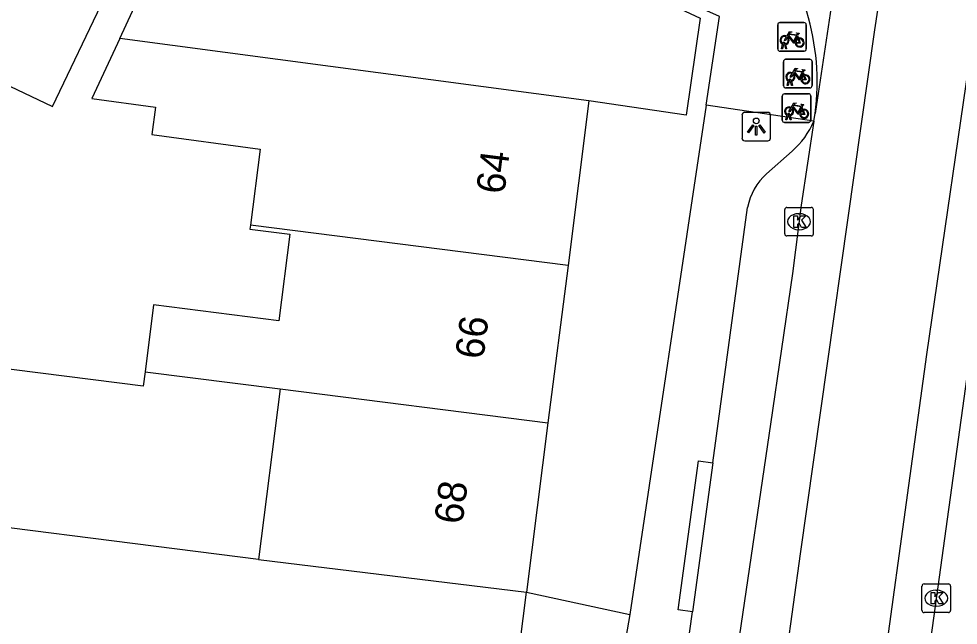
# Model space of a CAD drawing. Extents: x 160356 to 161355, y 381727 to 382845.
# Drawn here: x 160853.83 to 160886.69, y 382411.12 to 382432.34 of the extents above; entities that cross this region are included whole.
import ezdxf

# ---------------------------------------------------------------- set-up
doc = ezdxf.new("R2010")
doc.units = 0
for name, color, linetype in [('IMGEO_Fietsenrek', 7, 'Continuous'), ('IMGEO_Kolk', 7, 'Continuous'), ('IMGEO_Lichtpunt', 7, 'Continuous'), ('IMGEO_Pand', 7, 'Continuous'), ('IMGEO_Pand_nummerreeks', 7, 'Continuous'), ('IMGEO_Rijbaan_lokaal_gesloten', 7, 'Continuous'), ('IMGEO_Rijbaan_lokaal_open', 7, 'Continuous'), ('IMGEO_Voetpad_open', 7, 'Continuous')]:
    doc.layers.add(name, color=color, linetype=linetype)

msp = doc.modelspace()

# ---------------------------------------------------------------- linework, layer by layer
at = {"layer": 'IMGEO_Fietsenrek'}
for p, q in [((160880.382, 382431.286), (160880.382, 382432.127)), ((160880.382, 382432.127), (160880.382, 382431.286)), ((160880.457, 382432.211), (160881.298, 382432.211)), ((160881.298, 382432.211), (160880.457, 382432.211)), ((160881.382, 382432.136), (160881.382, 382431.295)), ((160881.382, 382431.295), (160881.382, 382432.136)), ((160881.069, 382431.76), (160881.105, 382431.665)), ((160880.509, 382431.295), (160880.548, 382431.455)), ((160880.578, 382431.443), (160880.543, 382431.295)), ((160880.62, 382431.467), (160880.619, 382431.471)), ((160880.661, 382431.295), (160880.627, 382431.437)), ((160880.651, 382431.478), (160880.652, 382431.471)), ((160880.659, 382431.441), (160880.694, 382431.295)), ((160881.307, 382431.211), (160880.466, 382431.211)), ((160880.466, 382431.211), (160881.307, 382431.211)), ((160880.543, 382431.295), (160880.509, 382431.295)), ((160880.694, 382431.295), (160880.661, 382431.295)), ((160880.583, 382429.999), (160880.583, 382430.84)), ((160880.583, 382430.84), (160880.583, 382429.999)), ((160880.658, 382430.924), (160881.499, 382430.924)), ((160881.499, 382430.924), (160880.658, 382430.924)), ((160881.583, 382430.849), (160881.583, 382430.008)), ((160881.583, 382430.008), (160881.583, 382430.849)), ((160881.27, 382430.473), (160881.306, 382430.378)), ((160880.71, 382430.008), (160880.749, 382430.168)), ((160880.779, 382430.156), (160880.744, 382430.008)), ((160880.821, 382430.18), (160880.82, 382430.184)), ((160880.862, 382430.008), (160880.828, 382430.15)), ((160880.852, 382430.191), (160880.853, 382430.184)), ((160880.86, 382430.154), (160880.895, 382430.008)), ((160880.614, 382429.717), (160881.455, 382429.717)), ((160881.455, 382429.717), (160880.614, 382429.717)), ((160881.508, 382429.924), (160880.667, 382429.924)), ((160880.667, 382429.924), (160881.508, 382429.924)), ((160880.744, 382430.008), (160880.71, 382430.008)), ((160880.895, 382430.008), (160880.862, 382430.008)), ((160880.539, 382428.792), (160880.539, 382429.633)), ((160880.539, 382429.633), (160880.539, 382428.792)), ((160881.539, 382429.642), (160881.539, 382428.801)), ((160881.539, 382428.801), (160881.539, 382429.642)), ((160881.226, 382429.266), (160881.262, 382429.171)), ((160881.464, 382428.717), (160880.623, 382428.717)), ((160880.623, 382428.717), (160881.464, 382428.717)), ((160880.666, 382428.801), (160880.705, 382428.961)), ((160880.7, 382428.801), (160880.666, 382428.801)), ((160880.735, 382428.949), (160880.7, 382428.801)), ((160880.777, 382428.973), (160880.776, 382428.977)), ((160880.818, 382428.801), (160880.784, 382428.943)), ((160880.808, 382428.984), (160880.809, 382428.977)), ((160880.816, 382428.947), (160880.851, 382428.801)), ((160880.851, 382428.801), (160880.818, 382428.801))]:
    msp.add_line(p, q, dxfattribs=at)
for points in [[(160880.716, 382431.685), (160880.664, 382431.595), (160880.624, 382431.57), (160880.625, 382431.617), (160880.68, 382431.711)], [(160880.695, 382431.737), (160880.79, 382431.901), (160880.876, 382431.887), (160880.878, 382431.878), (160880.822, 382431.867), (160880.795, 382431.822), (160881.051, 382431.781)], [(160880.991, 382431.493), (160880.941, 382431.493), (160880.75, 382431.744), (160880.731, 382431.712)], [(160881.038, 382431.756), (160880.781, 382431.797), (160880.764, 382431.768), (160880.931, 382431.548), (160881.038, 382431.756)], [(160881.086, 382431.658), (160881.056, 382431.735), (160880.947, 382431.517), (160880.99, 382431.517)], [(160881.051, 382431.781), (160881.076, 382431.83), (160881.07, 382431.834), (160881.047, 382431.838), (160881.035, 382431.845), (160881.034, 382431.848), (160881.036, 382431.853), (160881.131, 382431.838), (160881.133, 382431.828), (160881.123, 382431.815), (160881.111, 382431.809), (160881.097, 382431.815), (160881.069, 382431.76)], [(160881.02, 382431.517), (160881.14, 382431.516), (160881.096, 382431.63)], [(160881.116, 382431.637), (160881.171, 382431.492), (160881.021, 382431.492)], [(160880.917, 382430.398), (160880.865, 382430.308), (160880.825, 382430.283), (160880.826, 382430.33), (160880.881, 382430.424)], [(160880.896, 382430.45), (160880.991, 382430.614), (160881.077, 382430.6), (160881.079, 382430.591), (160881.023, 382430.58), (160880.996, 382430.535), (160881.252, 382430.494)], [(160881.192, 382430.206), (160881.142, 382430.206), (160880.951, 382430.457), (160880.932, 382430.425)], [(160881.239, 382430.469), (160880.982, 382430.51), (160880.965, 382430.481), (160881.132, 382430.261), (160881.239, 382430.469)], [(160881.287, 382430.371), (160881.257, 382430.448), (160881.148, 382430.23), (160881.191, 382430.23)], [(160881.221, 382430.23), (160881.341, 382430.229), (160881.297, 382430.343)], [(160881.317, 382430.35), (160881.372, 382430.205), (160881.222, 382430.205)], [(160881.252, 382430.494), (160881.277, 382430.543), (160881.271, 382430.547), (160881.248, 382430.551), (160881.236, 382430.558), (160881.235, 382430.561), (160881.237, 382430.566), (160881.332, 382430.551), (160881.334, 382430.541), (160881.324, 382430.528), (160881.312, 382430.522), (160881.298, 382430.528), (160881.27, 382430.473)], [(160880.852, 382429.243), (160880.947, 382429.407), (160881.033, 382429.393), (160881.035, 382429.384), (160880.979, 382429.373), (160880.952, 382429.328), (160881.208, 382429.287)], [(160881.208, 382429.287), (160881.233, 382429.336), (160881.227, 382429.34), (160881.204, 382429.344), (160881.192, 382429.351), (160881.191, 382429.354), (160881.193, 382429.359), (160881.288, 382429.344), (160881.29, 382429.334), (160881.28, 382429.321), (160881.268, 382429.315), (160881.254, 382429.321), (160881.226, 382429.266)], [(160880.873, 382429.191), (160880.821, 382429.101), (160880.781, 382429.076), (160880.782, 382429.123), (160880.837, 382429.217)], [(160881.148, 382428.999), (160881.098, 382428.999), (160880.907, 382429.25), (160880.888, 382429.218)], [(160881.195, 382429.262), (160880.938, 382429.303), (160880.921, 382429.274), (160881.088, 382429.054), (160881.195, 382429.262)], [(160881.243, 382429.164), (160881.213, 382429.241), (160881.104, 382429.023), (160881.147, 382429.023)], [(160881.177, 382429.023), (160881.297, 382429.022), (160881.253, 382429.136)], [(160881.273, 382429.143), (160881.328, 382428.998), (160881.178, 382428.998)]]:
    msp.add_lwpolyline(points, dxfattribs=at)
for centre, radius, start, end in [((160880.46, 382432.133), 0.0779, 92.4484, 184.2845), ((160880.46, 382432.133), 0.0779, 92.4484, 184.2845), ((160881.304, 382432.133), 0.0779, 2.4484, 94.2845), ((160881.304, 382432.133), 0.0779, 2.4484, 94.2845), ((160880.622, 382431.596), 0.159, 62.6766, 242.1369), ((160880.622, 382431.596), 0.129, 63.3192, 238.903), ((160880.622, 382431.596), 0.129, 283.6043, 43.4302), ((160880.622, 382431.596), 0.159, 283.5766, 46.6042), ((160881.149, 382431.512), 0.159, 113.3408, 178.3217), ((160881.149, 382431.512), 0.159, 187.0065, 105.7708), ((160880.602, 382431.467), 0.0499, 12.8025, 158.6934), ((160880.622, 382431.596), 0.159, 253.9967, 271.7867), ((160880.602, 382431.467), 0.0174, 12.8025, 163.4502), ((160880.622, 382431.596), 0.129, 253.415, 269.0204), ((160881.149, 382431.512), 0.129, 113.923, 177.9556), ((160881.149, 382431.512), 0.129, 188.6715, 104.5883), ((160880.46, 382431.289), 0.0779, 182.4484, 274.2845), ((160880.46, 382431.289), 0.0779, 182.4484, 274.2845), ((160881.304, 382431.289), 0.0779, 272.4484, 4.2845), ((160881.304, 382431.289), 0.0779, 272.4484, 4.2845), ((160880.661, 382430.846), 0.0779, 92.4484, 184.2845), ((160880.661, 382430.846), 0.0779, 92.4484, 184.2845), ((160881.505, 382430.846), 0.0779, 2.4484, 94.2845), ((160881.505, 382430.846), 0.0779, 2.4484, 94.2845), ((160880.823, 382430.309), 0.159, 62.6766, 242.1369), ((160880.823, 382430.309), 0.129, 63.3192, 238.903), ((160880.823, 382430.309), 0.129, 283.6043, 43.4302), ((160880.823, 382430.309), 0.159, 283.5766, 46.6042), ((160881.35, 382430.225), 0.159, 113.3408, 178.3217), ((160881.35, 382430.225), 0.159, 187.0065, 105.7708), ((160881.35, 382430.225), 0.129, 113.923, 177.9556), ((160881.35, 382430.225), 0.129, 188.6715, 104.5883), ((160880.803, 382430.18), 0.0499, 12.8025, 158.6934), ((160880.823, 382430.309), 0.159, 253.9967, 271.7867), ((160880.803, 382430.18), 0.0174, 12.8025, 163.4502), ((160880.823, 382430.309), 0.129, 253.415, 269.0204), ((160880.617, 382429.639), 0.0779, 92.4484, 184.2845), ((160880.617, 382429.639), 0.0779, 92.4484, 184.2845), ((160880.661, 382430.002), 0.0779, 182.4484, 274.2845), ((160880.661, 382430.002), 0.0779, 182.4484, 274.2845), ((160881.461, 382429.639), 0.0779, 2.4484, 94.2845), ((160881.461, 382429.639), 0.0779, 2.4484, 94.2845), ((160881.505, 382430.002), 0.0779, 272.4484, 4.2845), ((160881.505, 382430.002), 0.0779, 272.4484, 4.2845), ((160880.779, 382429.102), 0.159, 62.6766, 242.1369), ((160880.779, 382429.102), 0.129, 63.3192, 238.903), ((160880.779, 382429.102), 0.129, 283.6043, 43.4302), ((160880.779, 382429.102), 0.159, 283.5766, 46.6042), ((160881.306, 382429.018), 0.159, 113.3408, 178.3217), ((160881.306, 382429.018), 0.159, 187.0065, 105.7708), ((160881.306, 382429.018), 0.129, 113.923, 177.9556), ((160881.306, 382429.018), 0.129, 188.6715, 104.5883), ((160880.617, 382428.795), 0.0779, 182.4484, 274.2845), ((160880.617, 382428.795), 0.0779, 182.4484, 274.2845), ((160880.759, 382428.973), 0.0499, 12.8025, 158.6934), ((160880.779, 382429.102), 0.159, 253.9967, 271.7867), ((160880.759, 382428.973), 0.0174, 12.8025, 163.4502), ((160880.779, 382429.102), 0.129, 253.415, 269.0204), ((160881.461, 382428.795), 0.0779, 272.4484, 4.2845), ((160881.461, 382428.795), 0.0779, 272.4484, 4.2845)]:
    msp.add_arc(centre, radius, start, end, dxfattribs=at)
at = {"layer": 'IMGEO_Kolk'}
for p, q in [((160880.626, 382424.815), (160880.626, 382425.667)), ((160880.701, 382425.741), (160881.553, 382425.741)), ((160881.114, 382425.521), (160881.139, 382425.521)), ((160881.627, 382425.667), (160881.627, 382424.815)), ((160881.137, 382424.961), (160881.112, 382424.961)), ((160881.553, 382424.741), (160880.701, 382424.741)), ((160885.428, 382411.634), (160885.428, 382412.486)), ((160885.503, 382412.56), (160886.355, 382412.56)), ((160885.916, 382412.34), (160885.941, 382412.34)), ((160886.429, 382412.486), (160886.429, 382411.634)), ((160885.939, 382411.78), (160885.914, 382411.78)), ((160886.355, 382411.56), (160885.503, 382411.56))]:
    msp.add_line(p, q, dxfattribs=at)
for points in [[(160880.626, 382424.815), (160880.626, 382425.667)], [(160880.701, 382425.741), (160881.553, 382425.741)], [(160880.947, 382425.441), (160881.07, 382425.441), (160881.07, 382425.29), (160881.2, 382425.441), (160881.364, 382425.441), (160881.218, 382425.29), (160881.371, 382425.041), (160881.219, 382425.041), (160881.134, 382425.205), (160881.07, 382425.138), (160881.07, 382425.041), (160880.947, 382425.041), (160880.947, 382425.441)], [(160881.627, 382425.667), (160881.627, 382424.815)], [(160881.553, 382424.741), (160880.701, 382424.741)], [(160885.428, 382411.634), (160885.428, 382412.486)], [(160885.503, 382412.56), (160886.355, 382412.56)], [(160886.429, 382412.486), (160886.429, 382411.634)], [(160885.749, 382412.26), (160885.872, 382412.26), (160885.872, 382412.109), (160886.002, 382412.26), (160886.166, 382412.26), (160886.02, 382412.109), (160886.173, 382411.86), (160886.021, 382411.86), (160885.936, 382412.024), (160885.872, 382411.957), (160885.872, 382411.86), (160885.749, 382411.86), (160885.749, 382412.26)], [(160886.355, 382411.56), (160885.503, 382411.56)]]:
    msp.add_lwpolyline(points, dxfattribs=at)
for centre, start, end in [((160880.703, 382425.665), 91.552, 178.448), ((160880.703, 382425.665), 91.552, 178.448), ((160881.551, 382425.665), 1.552, 88.448), ((160881.551, 382425.665), 1.552, 88.448), ((160880.703, 382424.817), 181.552, 268.448), ((160880.703, 382424.817), 181.552, 268.448), ((160881.551, 382424.817), 271.552, 358.448), ((160881.551, 382424.817), 271.552, 358.448), ((160885.505, 382412.484), 91.552, 178.448), ((160885.505, 382412.484), 91.552, 178.448), ((160886.353, 382412.484), 1.552, 88.448), ((160886.353, 382412.484), 1.552, 88.448), ((160885.505, 382411.636), 181.552, 268.448), ((160885.505, 382411.636), 181.552, 268.448), ((160886.353, 382411.636), 271.552, 358.448), ((160886.353, 382411.636), 271.552, 358.448)]:
    msp.add_arc(centre, 0.0765, start, end, dxfattribs=at)
for centre, major_axis, ratio, start_param, end_param in [((160881.113, 382425.241), (-0.387, 0.002), 0.722429, 4.712389, 7.853982), ((160881.138, 382425.241), (-0.39, 0.002), 0.717154, 1.570796, 4.712389), ((160885.915, 382412.06), (-0.387, 0.002), 0.722429, 4.712389, 7.853982), ((160885.94, 382412.06), (-0.39, 0.002), 0.717154, 1.570796, 4.712389)]:
    msp.add_ellipse(centre, major_axis=major_axis, ratio=ratio, start_param=start_param, end_param=end_param, dxfattribs=at)
at = {"layer": 'IMGEO_Lichtpunt'}
for p, q in [((160880.034, 382429.067), (160879.226, 382429.067)), ((160880.034, 382429.067), (160879.226, 382429.067)), ((160879.132, 382428.972), (160879.132, 382428.165)), ((160879.132, 382428.972), (160879.132, 382428.165)), ((160880.128, 382428.165), (160880.128, 382428.972)), ((160880.128, 382428.165), (160880.128, 382428.972)), ((160879.226, 382428.071), (160880.034, 382428.071)), ((160879.226, 382428.071), (160880.034, 382428.071))]:
    msp.add_line(p, q, dxfattribs=at)
for points in [[(160879.506, 382428.636), (160879.545, 382428.608), (160879.357, 382428.346), (160879.319, 382428.373), (160879.506, 382428.636)], [(160879.608, 382428.588), (160879.655, 382428.588), (160879.655, 382428.266), (160879.608, 382428.266), (160879.608, 382428.588)], [(160879.718, 382428.608), (160879.756, 382428.635), (160879.943, 382428.373), (160879.904, 382428.345), (160879.718, 382428.608)]]:
    msp.add_lwpolyline(points, dxfattribs=at)
msp.add_circle((160879.631, 382428.77), 0.0994, dxfattribs=at)
for centre, start, end in [((160879.226, 382428.972), 90, 180), ((160879.226, 382428.972), 90, 180), ((160880.034, 382428.972), 0, 90), ((160880.034, 382428.972), 0, 90), ((160879.226, 382428.165), 180, 270), ((160879.226, 382428.165), 180, 270), ((160880.034, 382428.165), 270, 0), ((160880.034, 382428.165), 270, 360)]:
    msp.add_arc(centre, 0.0946, start, end, dxfattribs=at)
at = {"layer": 'IMGEO_Pand'}
for points in [[(160844.542, 382425.78), (160847.534, 382424.359), (160849.014, 382427.472), (160850.819, 382431.268), (160855.018, 382429.271), (160856.844, 382433.112), (160856.069, 382433.471), (160857.557, 382436.557), (160859.705, 382441.072)], [(160857.365, 382431.653), (160858.701, 382434.532)], [(160874.377, 382434.208), (160874.342, 382433.93), (160877.67, 382432.369), (160877.181, 382428.975), (160873.776, 382429.466)], [(160857.365, 382431.653), (160856.39, 382429.554), (160858.62, 382429.248), (160858.489, 382428.298), (160862.273, 382427.785), (160861.935, 382425.121)], [(160873.776, 382429.466), (160857.365, 382431.653)], [(160873.776, 382429.466), (160873.046, 382423.712)], [(160861.935, 382425.121), (160861.918, 382424.983), (160863.319, 382424.806), (160862.934, 382421.771), (160858.552, 382422.327), (160858.255, 382419.983)], [(160873.046, 382423.712), (160861.935, 382425.121)], [(160873.046, 382423.712), (160872.346, 382418.197)], [(160858.255, 382419.983), (160858.191, 382419.481), (160850.893, 382420.407), (160849.711, 382417.879)], [(160858.255, 382419.983), (160862.976, 382419.385)], [(160862.976, 382419.385), (160862.22, 382413.42)], [(160862.976, 382419.385), (160872.346, 382418.197)], [(160872.346, 382418.197), (160871.595, 382412.277)], [(160862.22, 382413.42), (160848.442, 382415.167)], [(160862.22, 382413.42), (160871.595, 382412.277)], [(160869.655, 382396.98), (160871.595, 382412.277)]]:
    msp.add_lwpolyline(points, dxfattribs=at)
at = {"layer": 'IMGEO_Rijbaan_lokaal_gesloten'}
for points in [[(160908.748, 382586.303), (160907.994, 382582.53), (160905.633, 382566.169), (160902.092, 382536.989), (160901.158, 382529.153), (160899.617, 382517.022), (160897.813, 382502.989), (160895.895, 382489.251), (160892.108, 382463.874), (160890.141, 382451.415), (160889.059, 382444.497), (160885.584, 382420.595), (160883.453, 382405.054), (160882.6, 382398.989), (160881.485, 382391.022), (160880.076, 382382.874), (160879.223, 382378.677), (160878.01, 382373.759), (160876.305, 382367.268), (160874.812, 382362.252)], [(160871.549, 382363.225), (160872.864, 382367.516), (160875.093, 382376.203), (160878.093, 382391.995), (160879.468, 382401.203), (160881.177, 382413.62), (160883.781, 382431.953), (160885.906, 382445.891), (160887.065, 382452.22)], [(160884.594, 382448.404), (160881.688, 382429.028)], [(160888.323, 382429.899), (160888.221, 382429.209), (160887.753, 382425.309), (160885.402, 382408.232)], [(160881.647, 382428.757), (160881.688, 382429.028)], [(160881.647, 382428.757), (160881.202, 382425.818), (160880.898, 382423.426), (160880.13, 382418.151), (160879.045, 382410.779), (160878.312, 382405.748)]]:
    msp.add_lwpolyline(points, dxfattribs=at)
at = {"layer": 'IMGEO_Rijbaan_lokaal_open'}
msp.add_arc((160873.348, 382430.138), 8.413, 352.4184, 41.4843, dxfattribs=at)
at = {"layer": 'IMGEO_Voetpad_open'}
for points in [[(160877.876, 382429.319), (160878.34, 382432.421), (160874.377, 382434.208)], [(160877.876, 382429.319), (160875.211, 382411.49)], [(160881.647, 382428.757), (160877.876, 382429.319)], [(160879.99, 382426.916), (160880.886, 382427.71)], [(160878.106, 382416.795), (160879.326, 382425.742)], [(160877.395, 382411.585), (160876.901, 382411.656), (160877.612, 382416.866), (160878.106, 382416.795)], [(160878.106, 382416.795), (160877.395, 382411.585)], [(160871.595, 382412.277), (160875.211, 382411.49)], [(160875.211, 382411.49), (160870.226, 382382.815)], [(160877.055, 382409.091), (160877.395, 382411.585)]]:
    msp.add_lwpolyline(points, dxfattribs=at)
for centre, radius, start, end in [((160878.953, 382429.915), 2.932, 311.2385, 336.7393), ((160881.385, 382425.353), 2.095, 131.7305, 169.2856)]:
    msp.add_arc(centre, radius, start, end, dxfattribs=at)

# ---------------------------------------------------------------- texts
at = {"layer": 'IMGEO_Pand_nummerreeks'}
for s, rotation, p in [('64', 82.7695, (160870.818, 382426.178)), ('66', 82.7716, (160870.085, 382420.399)), ('68', 82.7716, (160869.353, 382414.623))]:
    msp.add_text(s, height=1, rotation=rotation, dxfattribs=at).set_placement(p)

doc.saveas('drawing.dxf')
